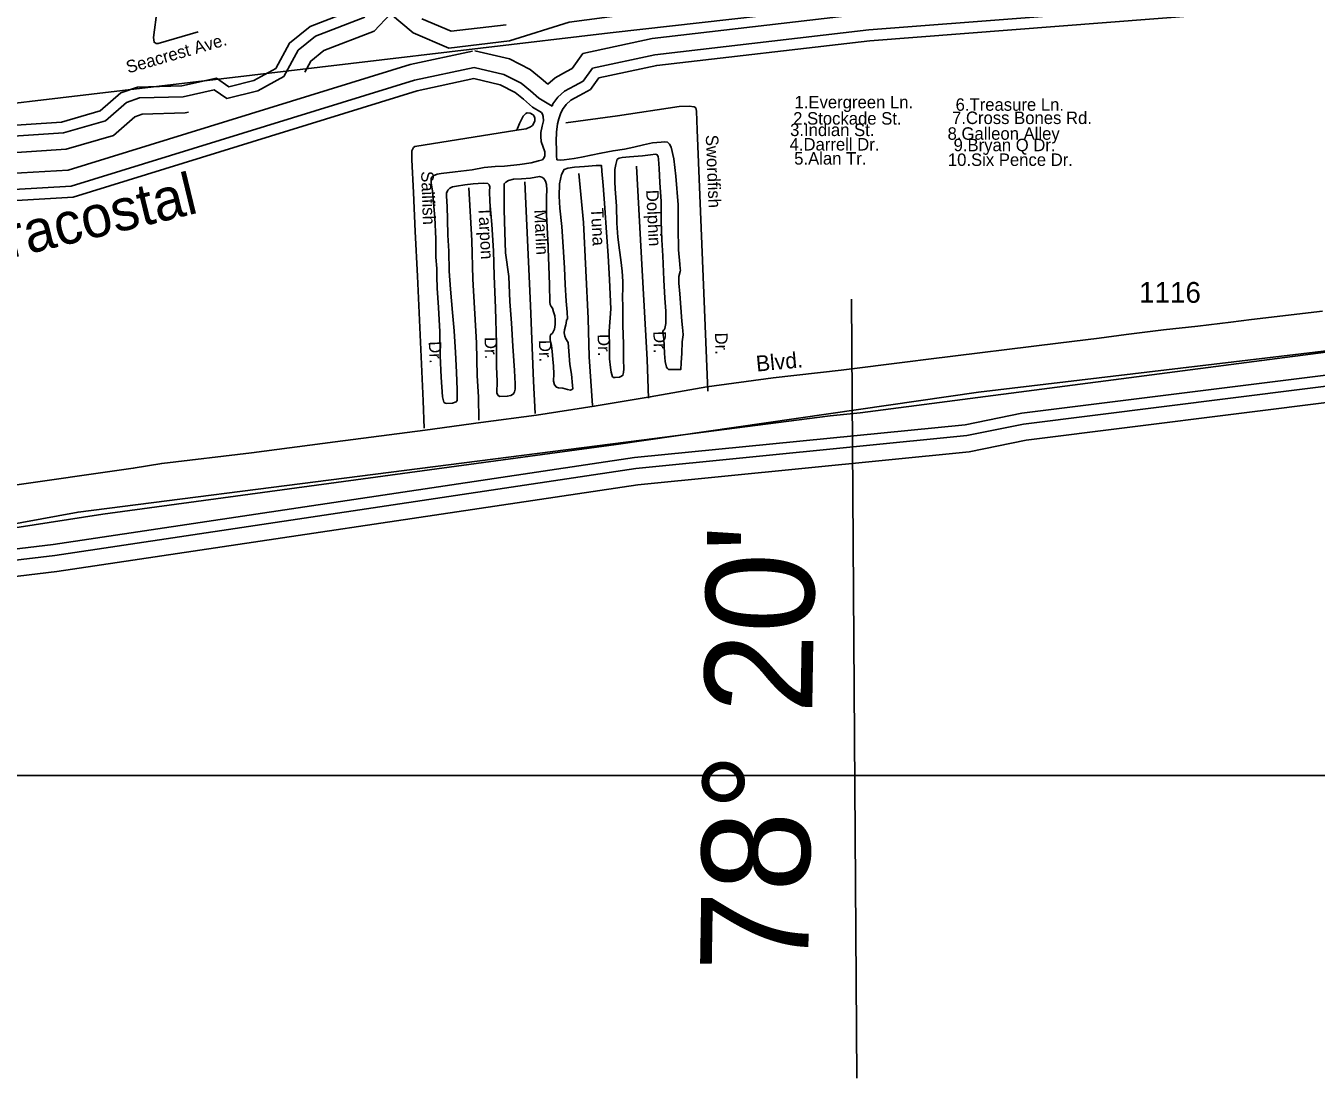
# Model space of a CAD drawing. Extents: x 2104537 to 2336408, y 34176 to 229611.
# Drawn here: x 2198609 to 2206373, y 54143 to 60476 of the extents above; entities that cross this region are included whole.
import ezdxf

# ---------------------------------------------------------------- set-up
doc = ezdxf.new("R2010")
doc.units = 0
for name, color, linetype in [('Exist Boundary Political City Limit New', 7, 'Continuous'), ('Exist Boundary Political CountyLine', 7, 'Continuous'), ('Exist Hydrographic Buffer Line', 7, 'Continuous'), ('Exist Hydrographic Creek Single Shore', 7, 'Continuous'), ('Exist Hydrographic Intracoastal Waterway Label', 7, 'Continuous'), ('Exist Road Non-System Type 51', 7, 'Continuous'), ('Exist Road Non-System Type 51 Label', 7, 'Continuous'), ('Exist Road Secondary Type 51 Attributed', 7, 'Continuous'), ('Exist Road Secondary Type 51 Label', 7, 'Continuous'), ('Exist Road Secondary Type 51 Number Label', 7, 'Continuous'), ('Map Preparation Boundary City Limit Buffer Line', 7, 'Continuous'), ('Map Preparation Inset Cut Line', 7, 'Continuous'), ('Map Preparation Longitude Latitude Label', 7, 'Continuous'), ('Map Preparation Longitude Latitude Lines', 7, 'Continuous')]:
    doc.layers.add(name, color=color, linetype=linetype)

msp = doc.modelspace()

# ---------------------------------------------------------------- linework, layer by layer
at = {"layer": 'Exist Boundary Political City Limit New'}
for points in [[(2190435.2, 57321.5), (2190540.2, 58145), (2190701.5, 58827.2), (2190746.5, 58940.8), (2190860.5, 59043.3), (2191017.2, 59149.3), (2191214, 59250.7), (2191462.8, 59339.5), (2191837.2, 59387.5), (2192241.2, 59378.3), (2192516.2, 59324.1), (2192761.5, 59327.3), (2202125.8, 60433.4), (2206426.8, 60920)], [(2207092.2, 58598.4), (2203629, 58147.7), (2203449.2, 58128.1), (2202312.8, 57982.7), (2198924.2, 57549.3), (2197709.8, 57326.3), (2197185, 57245.2), (2196877.2, 57173.3), (2196086.2, 57028), (2194751.5, 56573.8), (2194115.2, 56450), (2193378.5, 56219.9), (2191907.2, 56186.6), (2190791.8, 56532.8), (2190659.5, 56718.6), (2190435.2, 57321.5)]]:
    msp.add_lwpolyline(points, dxfattribs=at)
at = {"layer": 'Exist Boundary Political CountyLine'}
msp.add_lwpolyline([(2207092.1, 58598.4), (2204341.5, 58271.7), (2202161.9, 57956.8), (2199073.3, 57536.8), (2197185.1, 57245.2)], dxfattribs=at)
at = {"layer": 'Exist Hydrographic Buffer Line'}
for points in [[(2200288.2, 60197.9), (2200324.3, 60264.1), (2200402.6, 60326.9), (2200704.5, 60443.7), (2200802.5, 60547.3), (2200940.5, 60433.8), (2201153.5, 60341.9), (2201520.3, 60385.7), (2201878.3, 60497.2), (2202789, 60617.4), (2203547.4, 60639.3), (2203794.1, 60700.7), (2204197, 60928.2), (2204291.9, 60957.2), (2204595, 60936.1), (2205318.2, 60959.9), (2205608.9, 61056.7), (2205803.2, 61243.3), (2205918.5, 61288.9), (2206157.4, 61289.8), (2206476, 61239.7)], [(2201961.3, 60309.1), (2202378.1, 60399.1), (2203671.1, 60549.6), (2206519.3, 60770.3), (2207299.9, 60859), (2208310.5, 61056.9), (2208890.6, 61096.9), (2209413.3, 61056.4)], [(2202018.9, 60220.9), (2202394.2, 60301.9), (2203680.6, 60451.6), (2206528.7, 60672.3), (2207315, 60761.7), (2208323.4, 60959.1), (2208890.2, 60998.2), (2209404.1, 60958.4)], [(2197959, 59772.9), (2198835.2, 59830.9), (2199089.3, 59904.7), (2199214.3, 60014.9), (2199292.6, 60041.7), (2199555.8, 60049.5), (2199742.4, 60090.1), (2199818, 60038.9), (2200004.9, 60084.3), (2200161.4, 60170.7), (2200247.3, 60328.5), (2200352.9, 60413.3), (2200648.3, 60527.5)], [(2200992.3, 60518.7), (2201168.2, 60442.8), (2201499.7, 60482.3)], [(2194152.8, 58692.5), (2194404.8, 58727.5), (2194871, 58731.1), (2195204.3, 58853.2), (2195666.9, 58950.5), (2196367.2, 59154), (2196686.7, 59215.8), (2196979, 59318.6), (2197280.8, 59340.5), (2197359.7, 59317.1), (2197538.3, 59338.8), (2197911.4, 59485.4), (2198308, 59497.3), (2198514, 59587.5), (2198864.5, 59607.7), (2200922.2, 60243.2), (2201297.2, 60324.3)], [(2201749.5, 60124.8), (2201710.1, 60159), (2201644.5, 60213.6), (2201519.4, 60276.2), (2201310.5, 60325.7)], [(2201961.3, 60309.1), (2201895.8, 60218.7), (2201863.1, 60200.6), (2201793.5, 60163.7), (2201749.5, 60124.8)], [(2198537.3, 59490.3), (2198882.1, 59510.2), (2200947.2, 60147.9), (2201306.3, 60225.6)], [(2201775.3, 59992.8), (2201696.5, 60040.5), (2201646.3, 60084), (2201590.3, 60130.7), (2201485.6, 60183.1), (2201306.3, 60225.6)], [(2202018.9, 60220.9), (2201962.7, 60143.1), (2201910, 60114), (2201849.9, 60082.2), (2201810.3, 60047.2), (2201780.8, 60005.4), (2201775.3, 59992.8)], [(2194317.6, 58732), (2194410.5, 58777.4), (2194593.4, 58955.4), (2194818.5, 59070.5), (2195083.5, 59128.8), (2195249.6, 59191.1), (2195723.2, 59191.6), (2196177.8, 59305.6), (2196820, 59343.8), (2197053.5, 59460.7), (2197176.6, 59572.8), (2197533.6, 59637.7), (2197867.7, 59613.5), (2197986.4, 59676.1), (2198852.3, 59733.4), (2199137.8, 59816.3), (2199264.7, 59928.1), (2199310.4, 59943.7), (2199567.8, 59951.4), (2199587.4, 59955.7)], [(2190473.3, 56064.1), (2190668, 56002.3), (2191062.7, 55790.4), (2191496, 55679.8), (2192558.7, 55695.9), (2193066.5, 55766.2), (2193316.2, 55838.8), (2193544.2, 56018), (2194287.6, 56359), (2195087.9, 56587.6), (2196285.3, 56856.4), (2197230, 57103.1), (2198783.7, 57289.2), (2202279, 57812.3), (2204270.7, 58010.4), (2204612.5, 58079.4), (2208395.3, 58553.7), (2209303.3, 58585.5), (2209971.2, 58691.1), (2210712.4, 58762.2), (2211893.2, 58952.5), (2213341.5, 59039.4)]]:
    msp.add_lwpolyline(points, dxfattribs=at)
at = {"layer": 'Exist Hydrographic Creek Single Shore'}
for points in [[(2202057.3, 60162), (2202405, 60237.1), (2203686.9, 60386.3), (2206534.9, 60607), (2207325, 60696.8), (2208332, 60893.9), (2208889.9, 60932.4), (2209398.5, 60893)], [(2197940.8, 59837.5), (2198823.7, 59895.9), (2199056.9, 59963.6), (2199180.7, 60072.8), (2199280.8, 60106.9), (2199547.8, 60114.9), (2199755.9, 60160.1), (2199830.7, 60109.5), (2199980.8, 60146), (2200112.9, 60218.9), (2200195.9, 60371.5), (2200319.8, 60470.8), (2200610.8, 60583.3)], [(2198552.9, 59425.5), (2198893.9, 59445.1), (2200963.9, 60084.4), (2201305.6, 60158.3)], [(2201707.1, 59809.2), (2201707.6, 59833.8), (2201715.2, 59872), (2201723.1, 59904), (2201722.2, 59929.3), (2201718.9, 59943.5), (2201712.5, 59954.1), (2201657.7, 59987.3), (2201603.8, 60034), (2201554.1, 60075.4), (2201463, 60121), (2201305.6, 60158.3)], [(2202057.3, 60162), (2202007.2, 60092.8), (2201941.2, 60056.3), (2201887.5, 60027.8), (2201859.5, 60003.1), (2201838.2, 59973), (2201826.6, 59946.3), (2201816.5, 59917), (2201809, 59886.6), (2201803.1, 59835.9), (2201800.4, 59781.2), (2201802.7, 59727), (2201803, 59693.2), (2201805.2, 59669.5), (2201824.8, 59667.5), (2201849.1, 59669.3), (2201909.3, 59678), (2201953.4, 59686.3), (2202010.1, 59698.4), (2202069, 59709.4), (2202142.8, 59724.4), (2202210.6, 59732.9), (2202268.2, 59745.9), (2202326.3, 59760.2), (2202380, 59771.6), (2202432.2, 59775.5), (2202450.9, 59776.8), (2202470.3, 59775.5), (2202482.8, 59763.1), (2202492.7, 59746.5), (2202508, 59674.7), (2202520.5, 59572.1), (2202534.2, 59398.6), (2202533.5, 59260.8), (2202536.9, 59128.8), (2202544.1, 59042.4), (2202546.1, 59014.5), (2202548.3, 59004.6), (2202546.1, 58996.5), (2202538.7, 58966.4), (2202539.2, 58927), (2202543.9, 58863), (2202550.5, 58780.8), (2202555.5, 58698.7), (2202560, 58660.9), (2202563.2, 58641.1), (2202564.4, 58617.2), (2202558.7, 58574.6), (2202555.7, 58506.8), (2202552, 58448.4), (2202550.2, 58407.5), (2202498.4, 58408.5), (2202476.7, 58408.2), (2202469.6, 58413.3), (2202464.5, 58421.6), (2202456.7, 58456.2), (2202451.7, 58503.8), (2202449.3, 58549.8), (2202448.4, 58591.5), (2202442.2, 58627.7), (2202441.7, 58635.9), (2202443.8, 58641.8), (2202450.2, 58647.3), (2202453.9, 58655.4), (2202459.7, 58684.1), (2202460.8, 58757.9), (2202454.8, 58836.8), (2202447.1, 58947.5), (2202441, 59091.3), (2202436.3, 59187.2), (2202431.2, 59299.8), (2202432.2, 59417.9), (2202424.6, 59533.6), (2202419.3, 59617.3), (2202415.1, 59673.2), (2202413.5, 59689), (2202406.8, 59700.6), (2202397, 59703.1), (2202367.1, 59698.7), (2202319.1, 59694.1), (2202241.2, 59687.4), (2202198.1, 59683.3), (2202179.7, 59679.4), (2202167.4, 59673), (2202163.5, 59658.3), (2202159.6, 59640.4), (2202154.1, 59610.3), (2202152.4, 59592.9), (2202152.4, 59574.2), (2202152.6, 59552.9), (2202153.3, 59537.2), (2202155.1, 59494.5), (2202162.3, 59391), (2202165.3, 59288.6), (2202172.2, 59203.1), (2202180.8, 59124.9), (2202189.6, 59067.3)], [(2201646.5, 59559.4), (2201592.6, 59554.5), (2201544.4, 59552.2), (2201512.7, 59545.6), (2201496.5, 59535), (2201487.1, 59525.4), (2201487.8, 59423.7), (2201488.3, 59367.9), (2201492, 59234.9), (2201495.2, 59110.2), (2201514.7, 58966.4), (2201522, 58816), (2201531.6, 58686.3), (2201539.5, 58548.3), (2201548.8, 58402.1), (2201553.5, 58321), (2201553.2, 58289.9), (2201549.9, 58272.5), (2201544.1, 58260.5), (2201527.5, 58251.6), (2201505.8, 58247.1), (2201462.1, 58245.7), (2201451.4, 58251.5), (2201444.1, 58265.7), (2201445.2, 58337.9), (2201442.2, 58423.2), (2201441, 58565), (2201434.6, 58777.7), (2201426.6, 58971.4), (2201423.2, 59121.4), (2201413.5, 59280.7), (2201402, 59417.1), (2201399.3, 59481.1), (2201400.8, 59506.7), (2201397.1, 59518.9), (2201389, 59527.3), (2201360.8, 59528.8), (2201301.1, 59525.7), (2201251.1, 59519.4), (2201200.7, 59511.2), (2201177, 59506.7), (2201160.1, 59498.2), (2201149.1, 59486), (2201141.2, 59469), (2201139.5, 59450.1), (2201144.9, 59388.6), (2201147.3, 59310.5), (2201148.1, 59215.3), (2201155.1, 59120), (2201156.4, 59000.2), (2201163.5, 58890.2), (2201176.9, 58750.5), (2201186.6, 58640.4), (2201193.6, 58510.7), (2201200.5, 58391.8), (2201204, 58285.1), (2201204.4, 58234.9), (2201205.1, 58221.8), (2201198.7, 58213), (2201176.9, 58205.2), (2201142.7, 58202.6), (2201132.6, 58206.1), (2201125.2, 58211.2), (2201121.7, 58220.1), (2201116.6, 58242.5), (2201107.7, 58361.4), (2201101.7, 58490.5), (2201100.2, 58633.9), (2201092.8, 58780), (2201083.6, 58897.7), (2201082.7, 58968.2), (2201081.3, 59016.5), (2201075.7, 59083.8), (2201075.5, 59193.7), (2201070.8, 59323.4), (2201062.3, 59411.5), (2201055.5, 59481.2), (2201048.6, 59531.5), (2201048.4, 59559.4), (2201053.5, 59567.5), (2201060.5, 59573.9), (2201083.7, 59582.4), (2201108.4, 59587.8), (2201193.5, 59596.6), (2201294.2, 59609.5), (2201367.9, 59622.8), (2201433.6, 59629.1), (2201489.8, 59632), (2201581.8, 59641), (2201649.3, 59651.8), (2201693.1, 59662.5), (2201717.2, 59670.2), (2201724.6, 59678.3), (2201731.4, 59691.3), (2201732.6, 59718.5), (2201710.2, 59780.3), (2201707.1, 59809.2)], [(2202189.6, 59067.3), (2202198.1, 58999.2), (2202200.8, 58936.8), (2202201.4, 58897.4), (2202200, 58845), (2202200.5, 58784.9), (2202201.7, 58675), (2202205, 58559.5), (2202205.9, 58467.6), (2202207.1, 58411.8), (2202205.7, 58389.5), (2202202.1, 58373.2), (2202194.1, 58366.8), (2202180.9, 58361.4), (2202154.6, 58358.7), (2202146.1, 58360.5), (2202138.9, 58364.5), (2202130.6, 58392.6), (2202126.6, 58420.5), (2202122, 58472.5), (2202121, 58542), (2202118.3, 58638.2), (2202128.8, 58772.5), (2202121, 58948.2), (2202113.3, 59094.4), (2202102.2, 59232.4), (2202092.2, 59380.2), (2202083, 59515.5), (2202075.8, 59600.3), (2202073.8, 59634.8), (2202041.7, 59635.4), (2201969.7, 59628.6), (2201910.6, 59625.5), (2201870.1, 59619.7), (2201848, 59611.3), (2201832, 59581.1), (2201820.8, 59525.5), (2201818.7, 59451.1), (2201822.5, 59379.5), (2201833.5, 59267.7), (2201843, 59145.5), (2201850.4, 59019.7), (2201855.3, 58919.5), (2201860.3, 58819.4), (2201866.9, 58753.6), (2201867.5, 58713.6), (2201863.3, 58703.8), (2201859.7, 58685.9), (2201857.9, 58676), (2201850.1, 58645.7), (2201848.8, 58628.6), (2201852.6, 58607.9), (2201858.9, 58591.4), (2201872.9, 58569.8), (2201875.5, 58518.2), (2201882.2, 58437.7), (2201893.2, 58380.1), (2201899.4, 58311.7), (2201899.7, 58290.4), (2201895, 58286.6), (2201885.8, 58284.1), (2201867.8, 58287.7), (2201841.3, 58294.8), (2201813.8, 58297), (2201801.4, 58300.5), (2201790.5, 58314.8), (2201785.1, 58336.9), (2201786.9, 58381.2), (2201784.5, 58427.1), (2201780.1, 58469.2), (2201775.4, 58515.2), (2201771.8, 58553), (2201764.9, 58586.6), (2201764, 58605.7), (2201766.5, 58617.1), (2201778.2, 58626.7), (2201790.1, 58651.1), (2201793.9, 58678.9), (2201793.8, 58706.8), (2201791.7, 58730.5), (2201784.9, 58755.2), (2201778.8, 58776.7), (2201770.8, 58787.6), (2201764.1, 58799.2), (2201762.1, 58812.4), (2201759.2, 58916.5), (2201755.8, 59030.7), (2201750.6, 59186.6), (2201742.7, 59340), (2201741.8, 59448.3), (2201743.2, 59486), (2201742.9, 59520.4), (2201736.1, 59541.2), (2201726.5, 59556.2), (2201714.2, 59565.3), (2201700.5, 59568.2), (2201646.5, 59559.4)], [(2190540.2, 56111.7), (2190693.6, 56063), (2191086.7, 55852), (2191503.8, 55745.6), (2192553.6, 55761.4), (2193052.7, 55830.6), (2193285.7, 55898.3), (2193509.8, 56074.4), (2194264.8, 56420.7), (2195071.7, 56651.3), (2196269.8, 56920.2), (2197217.8, 57167.7), (2198774.9, 57354.2), (2202270.9, 57877.5), (2204260.9, 58075.4), (2204601.9, 58144.2), (2208390, 58619.2), (2209297, 58651), (2209963, 58756.2), (2210704, 58827.3), (2211886, 59017.8), (2213335.1, 59104.7)], [(2190456.3, 55966.3), (2190629.5, 55911.3), (2191026.7, 55698), (2191484.4, 55581.2), (2192566.2, 55597.6), (2193087.1, 55669.7), (2193362, 55749.6), (2193595.9, 55933.4), (2194321.9, 56266.4), (2195112.2, 56492.2), (2196308.5, 56760.7), (2197248.4, 57006.1), (2198796.8, 57191.6), (2202291.1, 57714.6), (2204285.3, 57912.9), (2204628.4, 57982.2), (2208403.1, 58455.5), (2209312.7, 58487.4), (2209983.6, 58593.4), (2210724.9, 58664.5), (2211904, 58854.5), (2213351.2, 58941.3)]]:
    msp.add_lwpolyline(points, dxfattribs=at)
at = {"layer": 'Exist Road Non-System Type 51'}
for points in [[(2199454.4, 60758.8), (2199443.1, 60714.4), (2199412.1, 60624.1), (2199399, 60573.8), (2199378.4, 60405.6), (2199380.8, 60377.3), (2199393.5, 60369.8), (2199405.6, 60369.9), (2199646.8, 60439.1)], [(2201563.2, 59847.4), (2201619.5, 59856.5), (2201644.9, 59868.1), (2201657.6, 59876.8), (2201671.5, 59902.7), (2201671.5, 59920.8), (2201667.8, 59932.7), (2201661.8, 59941), (2201643.6, 59950.8), (2201625.6, 59952.2), (2201618, 59949), (2201601.5, 59931.3), (2201579.4, 59887.4), (2201563.2, 59847.4)], [(2202712.4, 58277.7), (2202649.5, 59849.1), (2202643.8, 59962.1), (2202640.9, 59981.5), (2202630.5, 59988.9), (2202600.1, 59992.8), (2202540.3, 59989.7), (2202169.8, 59933.8), (2201857.7, 59891.6)], [(2201005.4, 58055), (2201000, 58219.1), (2200966.2, 58969.1), (2200951.4, 59239.1), (2200942.8, 59473.2), (2200932.1, 59669.3), (2200931.2, 59723.1), (2200941.7, 59742.9), (2200950.1, 59749.3), (2201563.2, 59847.4)], [(2202355, 58235), (2202347.9, 58467.1), (2202316.9, 59003.2), (2202284.4, 59631.1)], [(2202018.5, 58191), (2201997.9, 58483.1), (2201993.1, 58715.1), (2201964.2, 59293.1), (2201935.8, 59587.3)], [(2201335.7, 58103.1), (2201332.5, 58242.9), (2201325.1, 58369), (2201320.4, 58568.9), (2201298.2, 58951.3), (2201293.5, 59183.3), (2201275.3, 59501.2)], [(2201674.1, 58143.2), (2201663, 58337), (2201645.6, 58793), (2201611.3, 59537.4)]]:
    msp.add_lwpolyline(points, dxfattribs=at)
at = {"layer": 'Exist Road Secondary Type 51 Attributed'}
msp.add_lwpolyline([(2206410.5, 58759.6), (2205984.5, 58708.5), (2205858.7, 58692.7), (2205660.8, 58667.8), (2205455.1, 58645.5), (2205230.2, 58617.5), (2205067.7, 58595.3), (2204820, 58566.5), (2204041.1, 58469.8), (2203913, 58454.7), (2203515.6, 58404.3), (2203105.4, 58357.1), (2202705.7, 58303.3), (2202366.3, 58243), (2202029.5, 58186.6), (2201682.2, 58132.9), (2201346.7, 58088.3), (2201012.5, 58042.4), (2200471.3, 57971.6), (2199968, 57906.9), (2199427.4, 57842.3), (2199255.3, 57813.4), (2198484.5, 57703.9)], dxfattribs=at)
at = {"layer": 'Map Preparation Boundary City Limit Buffer Line'}
for points in [[(2190435.2, 57321.5), (2190540.2, 58145), (2190701.5, 58827.2), (2190746.5, 58940.8), (2190860.5, 59043.3), (2191017.2, 59149.3), (2191214, 59250.7), (2191462.8, 59339.5), (2191837.2, 59387.5), (2192241.2, 59378.3), (2192516.2, 59324.1), (2192761.5, 59327.3), (2202125.8, 60433.4), (2206426.8, 60920)], [(2207092.2, 58598.4), (2203629, 58147.7), (2203449.2, 58128.1), (2202312.8, 57982.7), (2198924.2, 57549.3), (2197709.8, 57326.3), (2197185, 57245.2), (2196877.2, 57173.3), (2196086.2, 57028), (2194751.5, 56573.8), (2194115.2, 56450), (2193378.5, 56219.9), (2191907.2, 56186.6), (2190791.8, 56532.8), (2190659.5, 56718.6), (2190435.2, 57321.5)]]:
    msp.add_lwpolyline(points, dxfattribs=at)
at = {"layer": 'Map Preparation Inset Cut Line'}
msp.add_lwpolyline([(2262949.2, 100213), (2187500, 100213), (2187500, 55964.5), (2244094.4, 55964.5), (2244094.4, 70118.4), (2262949.2, 70118.4)], close=True, dxfattribs=at)
at = {"layer": 'Map Preparation Longitude Latitude Lines'}
msp.add_line((2203608.9, 54143.1), (2203577.4, 58830.5), dxfattribs=at)

# ---------------------------------------------------------------- texts
at = {"layer": 'Exist Hydrographic Intracoastal Waterway Label'}
msp.add_text('Intracostal', height=250, rotation=13.63343, dxfattribs=at).set_placement((2198156.1, 58988.9))
at = {"layer": 'Exist Road Non-System Type 51 Label'}
for s, rotation, p in [('Seacrest Ave.', 16.00447, (2199225.1, 60188.9)), ('Swordfish', 272.29244, (2202700, 59818.6)), ('Sailfish', 272.10696, (2200987.4, 59600.2)), ('Dolphin', 272.96496, (2202341.1, 59487.1)), ('Tarpon', 273.26843, (2201331.2, 59386)), ('Marlin', 272.63162, (2201668.4, 59368.6)), ('Tuna', 272.86161, (2202009.2, 59378.8)), ('Dr.', 271.34074, (2202384.9, 58637.9)), ('Dr.', 271.34074, (2202755.9, 58629)), ('Dr.', 272.57908, (2201033.2, 58576.1)), ('Dr.', 271.34074, (2201368.8, 58602.5)), ('Dr.', 271.34074, (2201695.7, 58584.8)), ('Dr.', 271.34074, (2202049.1, 58620.2))]:
    msp.add_text(s, height=75, rotation=rotation, dxfattribs=at).set_placement(p)
for s, p in [('1.Evergreen Ln.', (2203234.2, 59979.4)), ('6.Treasure Ln.', (2204203.4, 59964.6)), ('2.Stockade St.', (2203226.1, 59881.4)), ('7.Cross Bones Rd.', (2204182, 59884.8)), ('3.Indian St.', (2203207.7, 59812.3)), ('8.Galleon Alley', (2204155.2, 59790.2)), ('4.Darrell Dr.', (2203204.7, 59725.4)), ('9.Bryan Q Dr.', (2204191.5, 59721.2)), ('5.Alan Tr.', (2203232.3, 59640.7)), ('10.Six Pence Dr.', (2204156.8, 59632.7))]:
    msp.add_text(s, height=75, dxfattribs=at).set_placement(p)
at = {"layer": 'Exist Road Secondary Type 51 Label'}
msp.add_text('Blvd.', height=95, rotation=5.37219, dxfattribs=at).set_placement((2203006.9, 58394.9))
at = {"layer": 'Exist Road Secondary Type 51 Number Label'}
msp.add_text('1116', height=125, dxfattribs=at).set_placement((2205307.2, 58809.4))
at = {"layer": 'Map Preparation Longitude Latitude Label'}
msp.add_text("78° 20'", height=650, rotation=89.07708, dxfattribs=at).set_placement((2203315.3, 54777.7))

doc.saveas('drawing.dxf')
